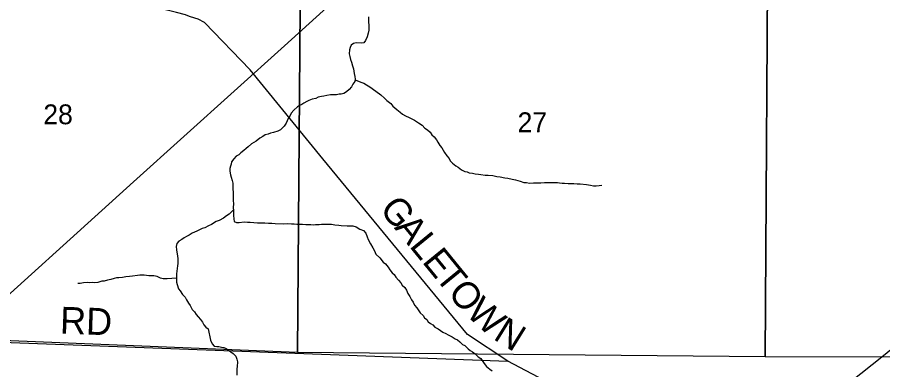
# Model space of a CAD drawing. Extents: x -8.5 to 18.7, y -20.3 to 7.
# Drawn here: x 4.267 to 7.92, y -8.863 to -7.375 of the extents above; entities that cross this region are included whole.
import ezdxf

# ---------------------------------------------------------------- set-up
doc = ezdxf.new("R2010")
doc.units = 0
for name, color, linetype in [('GM_X_County_Road', 7, 'Continuous'), ('GM_X_Minor_River', 7, 'Continuous'), ('GM_X_Rail_Line', 7, 'Continuous'), ('GM_X_Section', 7, 'Continuous'), ('GM_X_Section_Text', 7, 'Continuous'), ('GM_X_Township_Road', 7, 'Continuous'), ('GM_X_Township_Road_Text', 7, 'Continuous')]:
    doc.layers.add(name, color=color, linetype=linetype)

msp = doc.modelspace()

# ---------------------------------------------------------------- linework, layer by layer
at = {"layer": 'GM_X_County_Road'}
msp.add_lwpolyline([(5.5688, -10.8011), (5.8267, -10.5683), (6.2139, -10.1961), (6.4944, -9.937), (6.7242, -9.7652), (6.8562, -9.6754), (7.0642, -9.5212), (7.2089, -9.3842), (7.3538, -9.2453), (7.732, -8.955), (7.9241, -8.8029), (8.1243, -8.6374), (8.3921, -8.4103), (8.6752, -8.1728), (8.949, -7.9705)], dxfattribs=at)
at = {"layer": 'GM_X_Minor_River'}
for points in [[(5.7497, -7.3725), (5.7503, -7.3854), (5.7502, -7.396), (5.7508, -7.4059), (5.7513, -7.4287), (5.7489, -7.4416), (5.7442, -7.4574), (5.7372, -7.4726), (5.7302, -7.4824), (5.7203, -7.4838), (5.6976, -7.482), (5.6862, -7.4857), (5.677, -7.4917), (5.6723, -7.5022), (5.6692, -7.5121), (5.6682, -7.5288), (5.6704, -7.5402), (5.674, -7.5531), (5.6777, -7.5638), (5.6821, -7.5798), (5.6865, -7.5927), (5.6879, -7.6026), (5.6893, -7.6125), (5.6922, -7.6247), (5.6936, -7.6353), (5.6927, -7.6452), (5.6842, -7.6565), (5.6773, -7.6678), (5.6688, -7.6791), (5.6566, -7.6888), (5.6458, -7.6971), (5.6344, -7.6992), (5.6253, -7.6999), (5.6147, -7.7021), (5.5988, -7.7019), (5.5889, -7.7025), (5.5744, -7.7054), (5.5608, -7.7075), (5.5516, -7.7097), (5.5379, -7.7126), (5.528, -7.7171), (5.5121, -7.7207), (5.4983, -7.7259), (5.4892, -7.7303), (5.477, -7.7378), (5.4678, -7.743), (5.4587, -7.7467), (5.4495, -7.7527), (5.4349, -7.7669), (5.4234, -7.7797), (5.4172, -7.7918), (5.4102, -7.8016), (5.4017, -7.8212), (5.3932, -7.8341), (5.3786, -7.8499), (5.3664, -7.855), (5.3489, -7.8609), (5.3367, -7.8638), (5.326, -7.8683), (5.3139, -7.8712), (5.3032, -7.8779), (5.2909, -7.8854), (5.2756, -7.8981), (5.2565, -7.9085), (5.242, -7.922), (5.2328, -7.928), (5.2236, -7.937), (5.2113, -7.9468), (5.2021, -7.955), (5.1914, -7.9617), (5.1807, -7.9722), (5.1715, -7.9843), (5.1698, -7.9942), (5.1667, -8.0032), (5.1651, -8.0131), (5.1642, -8.0245), (5.1678, -8.0397), (5.17, -8.0496), (5.1744, -8.0633), (5.1773, -8.0747), (5.1771, -8.0869), (5.1777, -8.0998), (5.1791, -8.1127), (5.1787, -8.1491), (5.1793, -8.1613), (5.1783, -8.1787), (5.1797, -8.1894), (5.1803, -8.2031), (5.1802, -8.2122), (5.1809, -8.2251), (5.183, -8.2365), (5.1928, -8.2411)], [(5.6933, -7.6387), (5.7169, -7.6492), (5.7298, -7.6524), (5.7411, -7.6601), (5.7554, -7.6686), (5.7802, -7.6871), (5.8021, -7.7018), (5.8178, -7.7156), (5.8268, -7.7256), (5.8441, -7.7387), (5.8531, -7.7494), (5.8689, -7.764), (5.8832, -7.7755), (5.8929, -7.7832), (5.9065, -7.7902), (5.9208, -7.798), (5.9435, -7.8096), (5.9608, -7.8196), (5.9766, -7.8304), (5.9871, -7.8427), (5.9991, -7.8504), (6.0104, -7.8597), (6.0171, -7.8711), (6.0269, -7.8796), (6.0366, -7.8918), (6.0426, -7.9025), (6.0515, -7.9163), (6.059, -7.9262), (6.0642, -7.9354), (6.0709, -7.9453), (6.0798, -7.9599), (6.0903, -7.9714), (6.0948, -7.9813), (6.1038, -7.9905), (6.1188, -8.002), (6.1286, -8.0075), (6.1429, -8.0182), (6.1565, -8.026), (6.1655, -8.0276), (6.1746, -8.0307), (6.1882, -8.0332), (6.1996, -8.0356), (6.2147, -8.0372), (6.2238, -8.0381), (6.2428, -8.0413), (6.2549, -8.0415), (6.2739, -8.0432), (6.292, -8.0464), (6.3049, -8.0481), (6.3246, -8.0521), (6.3382, -8.0537), (6.3564, -8.0585), (6.37, -8.0609), (6.3798, -8.0641), (6.3904, -8.0672), (6.4048, -8.0719), (6.4169, -8.0728), (6.4298, -8.0745), (6.4465, -8.0739), (6.4579, -8.074), (6.4768, -8.0734), (6.4928, -8.0721), (6.5026, -8.0722), (6.5117, -8.0715), (6.536, -8.0718), (6.5474, -8.0727), (6.5565, -8.0735), (6.5678, -8.0744), (6.5777, -8.0745), (6.5921, -8.0762), (6.6171, -8.0765), (6.6308, -8.0774), (6.6437, -8.0775), (6.6694, -8.0808), (6.6861, -8.084), (6.699, -8.0865), (6.7103, -8.0858), (6.724, -8.0844), (6.7339, -8.0838)], [(5.1794, -8.1869), (5.1621, -8.2059), (5.1499, -8.2134), (5.1376, -8.2223), (5.1201, -8.232), (5.1064, -8.2372), (5.0865, -8.2499), (5.0751, -8.2551), (5.0583, -8.2632), (5.0476, -8.2662), (5.0362, -8.2714), (5.0247, -8.2781), (5.0049, -8.2862), (4.9927, -8.2952), (4.982, -8.2996), (4.9713, -8.3056), (4.9614, -8.3123), (4.9499, -8.3205), (4.9414, -8.3303), (4.9375, -8.3424), (4.9389, -8.3561), (4.9431, -8.3835), (4.9445, -8.3934), (4.9443, -8.4139), (4.9434, -8.4237), (4.9425, -8.4359), (4.9409, -8.4472), (4.94, -8.4571), (4.9391, -8.467), (4.9388, -8.4935), (4.9425, -8.5034), (4.9484, -8.521), (4.9543, -8.5301), (4.964, -8.5454), (4.9753, -8.5569), (4.9812, -8.5669), (4.9902, -8.5814), (4.9969, -8.5921), (5.0058, -8.6081), (5.0155, -8.6189), (5.0223, -8.6296), (5.0312, -8.6388), (5.041, -8.651), (5.0492, -8.6617), (5.0544, -8.6732), (5.0634, -8.6824), (5.0731, -8.6901), (5.0832, -8.738), (5.0899, -8.7533), (5.0981, -8.7632), (5.1095, -8.7641), (5.1186, -8.7642), (5.1292, -8.7681), (5.139, -8.769), (5.1496, -8.7729), (5.1594, -8.7806), (5.1692, -8.7868), (5.1782, -8.7937), (5.1894, -8.806), (5.1938, -8.8182), (5.1967, -8.8296), (5.1958, -8.8486), (5.1941, -8.8584), (5.1938, -8.885)], [(5.1928, -8.2411), (5.2034, -8.2405), (5.2247, -8.2377), (5.2391, -8.2401), (5.2505, -8.2402), (5.2664, -8.2412), (5.2808, -8.2421), (5.296, -8.243), (5.3127, -8.2424), (5.3271, -8.2433), (5.3415, -8.2435), (5.3551, -8.2459), (5.3923, -8.2463), (5.4082, -8.2457), (5.4241, -8.2467), (5.4355, -8.2468), (5.4469, -8.2477), (5.4712, -8.2479), (5.4856, -8.2496), (5.5068, -8.2498), (5.5166, -8.2507), (5.5258, -8.25), (5.5409, -8.2494), (5.5508, -8.2488), (5.5629, -8.2482), (5.5736, -8.2475), (5.5842, -8.2484), (5.5941, -8.2485), (5.6077, -8.2509), (5.6251, -8.2526), (5.635, -8.2535), (5.6592, -8.2553), (5.6835, -8.2555), (5.6971, -8.2595), (5.7137, -8.2695), (5.728, -8.2742), (5.7385, -8.2857), (5.7444, -8.301), (5.7488, -8.3132), (5.7577, -8.3315), (5.7674, -8.3475), (5.7748, -8.3605), (5.78, -8.3742), (5.798, -8.3896), (5.8115, -8.408), (5.8213, -8.4157), (5.8332, -8.4295), (5.8399, -8.4409), (5.8497, -8.4532), (5.8587, -8.4601), (5.8646, -8.4723), (5.8766, -8.4846), (5.8856, -8.4953), (5.8923, -8.5053), (5.9036, -8.516), (5.9095, -8.5267), (5.9162, -8.5404), (5.9236, -8.5542), (5.9318, -8.5679), (5.9385, -8.5771), (5.9444, -8.5901), (5.9542, -8.6008), (5.9676, -8.6222), (5.9811, -8.6338), (5.9863, -8.6429), (5.9953, -8.6506), (6.0013, -8.6598), (6.0118, -8.6675), (6.0209, -8.6737), (6.0291, -8.6829), (6.0434, -8.6906), (6.054, -8.6968), (6.063, -8.7045), (6.0766, -8.7092), (6.0864, -8.7154), (6.103, -8.7239), (6.1158, -8.7324), (6.1256, -8.7371), (6.1354, -8.7447), (6.1466, -8.7555), (6.1564, -8.7609), (6.1699, -8.774), (6.179, -8.7817), (6.188, -8.7878), (6.2, -8.7956), (6.2128, -8.8086), (6.2241, -8.8155), (6.2375, -8.8362), (6.2472, -8.8492), (6.2623, -8.86), (6.272, -8.8677)], [(4.939, -8.4768), (4.9003, -8.4787), (4.8836, -8.4785), (4.8723, -8.4754), (4.8579, -8.4691), (4.8435, -8.4667), (4.8231, -8.4657), (4.8034, -8.4632), (4.7844, -8.4638), (4.7753, -8.4652), (4.754, -8.468), (4.7403, -8.4694), (4.7259, -8.47), (4.7115, -8.4729), (4.6955, -8.4742), (4.6857, -8.4749), (4.6758, -8.477), (4.6621, -8.4814), (4.6476, -8.4843), (4.6339, -8.4887), (4.624, -8.4894), (4.6073, -8.4945), (4.5921, -8.4951), (4.583, -8.495), (4.5716, -8.4957), (4.5625, -8.4948), (4.5474, -8.4954), (4.5321, -8.4983), (4.5223, -8.4989)]]:
    msp.add_lwpolyline(points, dxfattribs=at)
at = {"layer": 'GM_X_Rail_Line'}
msp.add_lwpolyline([(1.838, -10.6862), (2.1974, -10.3661), (2.8053, -9.8305), (3.4123, -9.2873), (4.0286, -8.7279), (4.7575, -8.0687), (5.3952, -7.4956), (6.8786, -6.1515), (7.9737, -5.1713), (8.488, -4.679), (8.8174, -4.395), (9.2327, -4.0082), (9.3799, -3.8857)], dxfattribs=at)
at = {"layer": 'GM_X_Section'}
for points in [[(5.4662, -6.7863), (5.4507, -8.7904), (3.4092, -8.7072), (3.4403, -6.7639)], [(7.4371, -6.7861), (7.4236, -8.8084), (5.4507, -8.7904), (5.4662, -6.7863)], [(7.4371, -6.7861), (9.4685, -6.7898), (9.4459, -8.8098), (7.4236, -8.8084)]]:
    msp.add_lwpolyline(points, close=True, dxfattribs=at)
at = {"layer": 'GM_X_Township_Road'}
for points in [[(5.5575, -7.9719), (5.2496, -7.5967), (5.0569, -7.3961), (5.0305, -7.382), (4.998, -7.3724), (4.9875, -7.3691), (4.9769, -7.3637), (4.9399, -7.3547), (4.7909, -7.3174), (4.1748, -7.1472), (4.0087, -7.0875), (3.9421, -7.072), (3.5416, -7.0512), (3.3143, -6.8789), (3.1173, -6.7101), (3.0288, -6.5445), (2.9343, -6.3782), (2.9295, -6.3006), (2.9288, -6.1532)], [(7.1936, -9.3721), (7.0302, -9.2418), (6.787, -9.0687), (6.644, -8.9882), (6.3384, -8.826), (6.167, -8.7146), (5.5575, -7.9719)], [(2.4374, -8.6715), (3.4162, -8.7161), (6.3384, -8.826)]]:
    msp.add_lwpolyline(points, dxfattribs=at)

# ---------------------------------------------------------------- texts
at = {"layer": 'GM_X_Section_Text'}
for s, p in [('28', (4.3773, -7.8263)), ('27', (6.379, -7.8597))]:
    msp.add_text(s, height=0.08371, rotation=0, dxfattribs=at).set_placement(p)
at = {"layer": 'GM_X_Township_Road_Text'}
for s, height, rotation, p in [('G', 0.1136, 309.2384, (5.7928, -8.1865)), ('A', 0.1136, 309.2373, (5.856, -8.264)), ('L', 0.1136, 309.2383, (5.9193, -8.3414)), ('E', 0.1136, 309.2388, (5.9731, -8.4072)), ('T', 0.1136, 309.2388, (6.0268, -8.4731)), ('O', 0.1136, 309.3969, (6.0808, -8.5392)), ('W', 0.1136, 317.7868, (6.1568, -8.6296)), ('RD', 0.11364, 358.0252, (4.4464, -8.7101)), ('N', 0.1136, 328.1353, (6.2722, -8.7316))]:
    msp.add_text(s, height=height, rotation=rotation, dxfattribs=at).set_placement(p)

doc.saveas('drawing.dxf')
